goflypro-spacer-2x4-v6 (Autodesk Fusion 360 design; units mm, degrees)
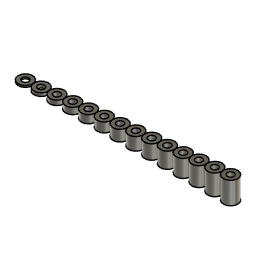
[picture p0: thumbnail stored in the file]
sketch "Skizze" plane through (0, 0, 0) normal (0, 0, 1) x axis (1, 0, 0)
  circle C1 centre (0, 0) radius 1.05
  circle C2 centre (0, 0) radius 2.25
  circle C3 centre (10, 0) radius 1.05
  circle C4 centre (10, 0) radius 2.25
  circle C5 centre (5, 0) radius 1.05
  circle C6 centre (5, 0) radius 2.25
  circle C7 centre (15, 0) radius 1.05
  circle C8 centre (15, 0) radius 2.25
  circle C9 centre (20, 0) radius 1.05
  circle C10 centre (20, 0) radius 2.25
  circle C11 centre (25, 0) radius 1.05
  circle C12 centre (25, 0) radius 2.25
  circle C13 centre (30, 0) radius 1.05
  circle C14 centre (30, 0) radius 2.25
  circle C15 centre (35, 0) radius 1.05
  circle C16 centre (35, 0) radius 2.25
  circle C17 centre (0, 0) radius 1.05
  circle C18 centre (0, 0) radius 2.25
  circle C19 centre (-5, 0) radius 1.05
  circle C20 centre (-5, 0) radius 2.25
  circle C21 centre (40, 0) radius 1.05
  circle C22 centre (40, 0) radius 2.25
  circle C23 centre (45, 0) radius 1.05
  circle C24 centre (45, 0) radius 2.25
  circle C25 centre (50, 0) radius 1.05
  circle C26 centre (50, 0) radius 2.25
  circle C27 centre (55, 0) radius 1.05
  circle C28 centre (55, 0) radius 2.25
  circle C29 centre (60, 0) radius 1.05
  circle C30 centre (60, 0) radius 2.25
  point P1 (0, 0)
  point P2 (0, 0)
  point P3 (0, 0)
  coincident P1 P2
  coincident P1 P3
  dimension "d1" diameter C1 = 2.1
  dimension "d2" diameter C2 = 4.5
  dimension "d5" diameter C3 = 2.1
  dimension "d6" diameter C4 = 4.5
  dimension "d7" diameter C5 = 2.1
  dimension "d8" diameter C6 = 4.5
  dimension "d9" diameter C7 = 2.1
  dimension "d10" diameter C8 = 4.5
  dimension "d11" diameter C9 = 2.1
  dimension "d12" diameter C10 = 4.5
  dimension "d13" diameter C11 = 2.1
  dimension "d14" diameter C12 = 4.5
  dimension "d15" diameter C13 = 2.1
  dimension "d16" diameter C14 = 4.5
  dimension "d17" diameter C15 = 2.1
  dimension "d18" diameter C16 = 4.5
  dimension "d21" diameter C17 = 2.1
  dimension "d22" diameter C18 = 4.5
  dimension "d37" diameter C20 = 4.5
  dimension "d38" diameter C19 = 2.1
  dimension "d41" diameter C21 = 2.1
  dimension "d42" diameter C22 = 4.5
  dimension "d43" diameter C23 = 2.1
  dimension "d44" diameter C24 = 4.5
  dimension "d45" diameter C25 = 2.1
  dimension "d46" diameter C26 = 4.5
  dimension "d47" diameter C27 = 2.1
  dimension "d48" diameter C28 = 4.5
  dimension "d49" diameter C29 = 2.1
  dimension "d50" diameter C30 = 4.5
extrude "Extrusion1" new body sketch "Skizze" profile of C1 C2 C17 C18 along normal blind 1 bodies "spacer 1mm"
extrude "Extrusion2" new body sketch "Skizze" profile of C5 C6 along normal blind 1.5 bodies "spacer 1.5mm"
extrude "Extrusion3" new body sketch "Skizze" profile of C3 C4 along normal blind 2 bodies "spacer 2mm"
extrude "Extrusion4" new body sketch "Skizze" profile of C7 C8 along normal blind 2.5 bodies "spacer 2.5mm"
extrude "Extrusion5" new body sketch "Skizze" profile of C9 C10 along normal blind 3 bodies "spacer 3mm"
extrude "Extrusion6" new body sketch "Skizze" profile of C11 C12 along normal blind 3.5 bodies "spacer 3.5mm"
extrude "Extrusion7" new body sketch "Skizze" profile of C13 C14 along normal blind 4 bodies "spacer 4mm"
extrude "Extrusion8" new body sketch "Skizze" profile of C15 C16 along normal blind 4.5 bodies "spacer 4.5mm"
extrude "Extrusion9" new body sketch "Skizze" profile of C19 C20 along normal blind 0.5 bodies "spacer 0.5mm"
extrude "Extrusion10" new body sketch "Skizze" profile of C21 C22 along normal blind 5 bodies "spacer 5mm"
extrude "Extrusion11" new body sketch "Skizze" profile of C23 C24 along normal blind 5.5 bodies "spacer 5.5mm"
extrude "Extrusion12" new body sketch "Skizze" profile of C25 C26 along normal blind 6 bodies "spacer 6mm"
extrude "Extrusion13" new body sketch "Skizze" profile of C27 C28 along normal blind 6.5 bodies "spacer 6.5mm"
extrude "Extrusion14" new body sketch "Skizze" profile of C29 C30 along normal blind 7 bodies "spacer 7mm"
named bodies: "spacer 1mm", "spacer 1.5mm", "spacer 2mm", "spacer 2.5mm", "spacer 3mm", "spacer 3.5mm", "spacer 4mm", "spacer 4.5mm", "spacer 0.5mm", "spacer 5mm", "spacer 5.5mm", "spacer 6mm", "spacer 6.5mm", "spacer 7mm"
